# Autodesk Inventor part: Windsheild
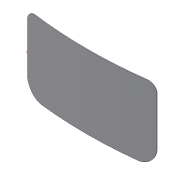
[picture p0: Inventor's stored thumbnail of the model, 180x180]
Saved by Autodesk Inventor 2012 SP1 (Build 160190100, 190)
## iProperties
Created: 2006-03
Part Number: Windsheild
Document SubType Name: Modeling
Mass: 10067 g
Surface Area: 25523.6 cm^2
Volume: 10067 cm^3
Density: 1 g/cm^3
Material: Default
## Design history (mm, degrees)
sketch "Sketch1"
  geometry: L1 (0, 6443.43)-(0, -556.57) reference; L2 (-900, 0)-(1200, 0) reference; A1 r 5000 centre (0, 4943.43) between (-750, 0) and (750, 0); 1 further point
  constraints: 3 point on line, 2 point on circle, 1 centre point
  dimensions: "d0" = 1500 distance of A1.end A1.start; "d2" = 5000 radius of A1
workplane "Work Plane1"
sketch "Sketch2"
  geometry: L1 (-4, 425)-(4, 425); L2 (4, 425)-(4, -425); L3 (4, -425)-(-4, -425); L4 (-4, -425)-(-4, 425); L5 (-4, 425)-(4, -425); 3 further points
  constraints: 10 end point, 2 parallel, 1 coincident, 1 horizontal, 1 midpoint, 1 perpendicular
  dimensions: "d3" = 8 distance of L1.start L1.end; "d4" = 850 distance of L1.end L2.end
sweep "Sweep1" sketch "Sketch2" dims "d5" = 0
fillet "Fillet1" dims "d6" = 100
fillet "Fillet2" dims "d7" = 200
body "Solid1"
